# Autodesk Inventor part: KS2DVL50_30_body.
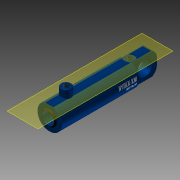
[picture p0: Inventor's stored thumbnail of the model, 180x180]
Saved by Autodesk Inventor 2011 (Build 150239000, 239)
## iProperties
Created: 2010-11
Document SubType Name: Modeling
Designer: TB
Mass: 405.061 g
Surface Area: 916.939 cm^2
Volume: 405.061 cm^3
Density: 1 g/cm^3
Author: TB
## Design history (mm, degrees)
sketch "Sketch2"
  geometry: L1 (-35, -3)-(-35, 3); L2 (-35, -9)-(-35, 9); L3 (-35, 0)-(-35, 30); L4 (-35, 30)-(-224, 30); L5 (-224, 30)-(-224, 30); L6 (-224, 30)-(-229, 30); L7 (-229, 30)-(-229, 19); L8 (-229, 19)-(-232, 16); L9 (-232, 16)-(-232, 15); L10 (-232, 15)-(-186, 15); L11 (-186, 15)-(-186, 25); L12 (-186, 25)-(-49, 25); L13 (-49, 25)-(-49, 0); L14 (-49, 0)-(-35, 0); L15 (-49, 0)-(-148.421, 0); L16 (-35, 9)-(-32, 12) reference; L17 (-32, 12)-(-35, 12) reference; L18 (-35, 12)-(-35, 9) reference; L19 (-32, 12)-(-35, 9) reference; L20 (-32, 12)-(-35, 12) reference; L21 (-35, 9)-(-35, 12) reference; L22 (-35, 9)-(-32, 12) reference; 1 further point
  constraints: 44 end point, 8 perpendicular, 6 parallel, 5 collinear, 2 horizontal, 2 vertical, 1 coincident, 1 midpoint, 1 point on line, 10 other
  dimensions: "DiaY" = 60 diameter of L4 L15; "DiaI" = 50 diameter of L12 L15; "d4" = 1 distance of L8.end L9.end; "d5" = 45 deg angle of L10 L8; "d6" = 3 distance between parallel lines of L7 L9; "DiaStang" = 30 diameter of L10 L15; "RindDia" = 60 diameter of L6 L15; "RingLengde" = 5 distance of L5.end L6.end; "RingTykk" = 43 distance between parallel lines of L11 L7; "KroppLengde" = 194 distance between parallel lines of L7 L3 (derived); "BunnTykkelse" = 14 distance between parallel lines of L13 L3
revolve "Kropp" sketch "Sketch2" stored, may be unused: angle "d13" = 90 deg
sketch "Sketch3"
  geometry: L1 (-49, -25)-(-49, 25) reference; L2 (-49, 0.01)-(-149, 0.01); L3 (-149, -0.01)-(-49, -0.01); A1 r 0.01 centre (-149, 0) between (-149, 0.01) and (-149, -0.01); A2 r 0.01 centre (-49, 0) between (-49, -0.01) and (-49, 0.01); 2 further points
  constraints: 4 end point, 4 point on circle, 4 tangent, 2 centre point, 1 coincident, 1 midpoint, 1 parallel, 1 perpendicular
  dimensions: "d17" = 0.01 radius of A2; "d18" = 100 distance of L2.start L2.end (= Slaglengde)
feature "BaneTransitionalConstraint" sketch "Sketch3" dims "d19" = 2, "d20" = 0
sketch "Sketch6"
  geometry: L1 (-42, 0)-(42, 0) reference; L2 (9.367, 28.5)-(-9.367, 28.5); L3 (30, 0)-(30, 31.248); L4 (-30, 0)-(-30, -18.451); A1 r 30 centre (0, 0) between (9.367, 28.5) and (-9.367, 28.5) reference; 1 further point
  constraints: 6 end point, 4 point on circle, 2 tangent
  dimensions: "d30" = 28.5 distance from line of A1.centre L2 (computed from DiaY); "d31" = 0 deg angle of L1 L2 (computed from Vinkel_Plussport); "d37" = 90 deg angle of L2 L3; "d38" = 90 deg angle of L2 L4
  node "Projected Loop3"
workplane "Work Plane5"
sketch "Sketch7"
  geometry: L1 (9.367, -278.4)-(9.367, 46.4) reference; L2 (-19.633, -35)-(38.367, -35) reference; C1 r 12.5 at (9.367, -52.5); 1 further point
  constraints: 1 centre point, 1 point on line
  dimensions: "PortDia" = 25 diameter of C1
extrude "Extrusion2" cut sketch "Sketch7" stored distance "d34" = 1.5; taper "d35" = 0 deg
workplane "Work Plane7"
sketch "Sketch4" dims "d142" = 12.20713
  geometry: L1 (-16.68, -40)-(-16.68, -78.777); L2 (-16.68, -78.777)-(16.68, -78.777); L3 (16.68, -78.777)-(16.68, -40); L4 (16.68, -40)-(-16.68, -40); L5 (-40.643, -40)-(0, -40); L6 (-29, -35)-(29, -35) reference; L7 (0, -35)-(0, -40); 3 further points
  constraints: 4 end point, 2 midpoint, 1 perpendicular, 2 other
  dimensions: "d40" = 5 distance of L7.start L5.end
emboss "Emboss1" sketch "Sketch4" dims "d4" = 1, "d5" = 45 deg, "d6" = 3, "d22" = 0.2, "d23" = 0, "DiaI" = 50, "DiaY" = 60, "RindDia" = 60, "DiaStang" = 30, "RingTykk" = 43, "RingLengde" = 5, "KroppLengde" = 194 (derived), "BunnTykkelse" = 14
workplane "Work Plane8"
sketch "Sketch8"
  geometry: L1 (-29, -35)-(29, -35) reference; L2 (0, -35)-(0, -40); L3 (-5.906, -110.587)-(-5.906, -40); L4 (-5.906, -40)-(5.906, -40); L5 (5.906, -40)-(5.906, -110.587); L6 (5.906, -110.587)-(-5.906, -110.587); 3 further points
  constraints: 2 end point, 2 midpoint, 1 perpendicular, 2 other
  dimensions: "d42" = 5 distance of L2.start L2.end
emboss "Emboss2" sketch "Sketch8" dims "d4" = 1, "d5" = 45 deg, "d6" = 3, "d43" = 0.2, "d44" = 0, "DiaI" = 50, "DiaY" = 60, "RindDia" = 60, "DiaStang" = 30, "RingTykk" = 43, "RingLengde" = 5, "KroppLengde" = 194 (derived), "BunnTykkelse" = 14
sketch "Sketch9"
  geometry: A1 r 12.5 centre (9.367, -52.5) between (0, -60.776) and (18.735, -60.776) reference; 1 further point
hole "Hole1" sketch "Sketch9" at (9.367, -52.5) diameter "d45" = 14.95; stored, may be unused: countersink angle "d49" = 82 deg, drill point angle "d51" = 118 deg; dims "d46" = 6, "d47" = 3.023, "d48" = 2, "d50" = 15
workplane "Work Plane9"
sketch "Sketch10"
  geometry: L1 (-42, 0)-(42, 0) reference; L2 (0, 30)-(13.136, 30); L3 (0, 30)-(0, 31.79); L4 (12.5, 27.272)-(12.5, 48); L5 (12.5, 48)-(0, 48); L6 (0, 48)-(0, 30); L7 (0, 30)-(12.5, 27.272); C1 r 30 at (0, 0) reference; A1 r 30 centre (0, 0) between (0, 30) and (12.5, 27.272); 1 further point
  constraints: 12 end point, 4 perpendicular, 2 concentric, 2 point on circle, 1 centre point, 1 point on line, 1 tangent
  dimensions: "d53" = 0 deg angle of L1 L2 (computed from Vinkel_Minusport); "d54" = 25 diameter of L4 L3; "d55" = 18 distance between parallel lines of L2 L5
revolve "Revolution2" sketch "Sketch10" stored, may be unused: angle "d56" = 90 deg
hole "Hole2" diameter "d59" = 14.95; stored, may be unused: countersink angle "d63" = 82 deg, drill point angle "d65" = 118 deg; dims "d57" = 10, "d58" = 10, "d60" = 6, "d61" = 3.023, "d62" = 2, "d64" = 14
fillet "Fillet1" dims "d66" = 2
sketch "Sketch15"
  geometry: L1 (12, -27.495)-(12, 27.495); L2 (-12, -27.495)-(-12, 27.495); A1 r 30 centre (0, 0) between (12, -27.495) and (-12, -27.495) reference; A2 r 29.998 centre (0, 0) between (12, 27.493) and (-12, 27.493); A3 r 29.998 centre (0, 0) between (-12, -27.493) and (12, -27.493)
  constraints: 8 point on circle, 4 end point, 4 point on line, 2 centre point
  dimensions: "d95" = 12 distance from line of L1 A1.centre; "d96" = 12 distance from line of A1.centre L2
extrude "Extrusion6" join sketch "Sketch15" distance "d97" = 62; taper "d98" = 0 deg
sketch "Sketch16"
  geometry: L1 (-35, 29.998)-(27, 29.998) reference; L2 (-35, -29.998)-(27, -29.998) reference; L3 (-228, -30)-(-35, -30) reference; L4 (-228, 30)-(-35, 30) reference; L5 (-35, 29.998)-(27, 29.998) reference; L6 (27, 29.998)-(27, 27.493) reference; L7 (27, -27.493)-(27, 27.493) reference; L8 (-279.911, 0)-(83.467, 0) reference; L9 (5.002, 29.998)-(27, 29.998); L10 (27, 29.998)-(27, 8); A1 r 21.998 centre (5.002, 8) between (27, 8) and (5.002, 29.998); 2 further points
  constraints: 4 end point, 4 tangent, 2 point on circle, 2 point on line, 1 centre point, 1 collinear, 1 perpendicular
  dimensions: "d137" = 8 distance from line of L10.end L8
extrude "Extrusion7" cut sketch "Sketch16" stored distance "d101" = 24; taper "d102" = 0 deg
mirror "Mirror1"
sketch "Sketch20"
  geometry: L1 (-35, 29.998)-(27, 29.998) reference; L2 (27, -27.493)-(27, 27.493) reference; L3 (27, 29.998)-(27, 27.493) reference; L4 (-47.543, 0)-(40.26, 0) reference; L5 (21.344, 15.366)-(2.962, 25.979); L6 (2.962, 25.979)-(-4, 29.998); A1 r 12.207 centre (15.24, 4.794) between (27, 8.069) and (21.344, 15.366); A2 r 30 centre (-12.038, -0.002) between (2.962, 25.979) and (-12.038, 29.998); 2 further points
  constraints: 4 end point, 4 point on circle, 3 point on line, 3 tangent, 2 centre point, 1 collinear, 1 midpoint
  dimensions: "d139" = 8.06884 distance from line of A1.start L4; "d140" = 22.66455 distance from line of L2 point (4.335, 0); "d141" = 30 deg angle of L1 L6; "d142" = 12.20713 radius of A1; "d143" = 30 radius of A2
extrude "Extrusion10" cut sketch "Sketch20" stored distance "d144" = 10; taper "d145" = 0 deg
mirror "Mirror2"
sketch "Sketch17"
  geometry: L1 (54.986, 0)-(0, 0) reference; L2 (27.493, -248.8)-(27.493, 113.8) reference; C1 r 18.5 at (27.493, 32); 1 further point
  constraints: 1 centre point, 1 point on line
  dimensions: "d103" = 37 diameter of C1; "d125" = 32 distance from line of C1.centre L1
extrude "Extrusion8" cut sketch "Sketch17" distance "d104" = 24; taper "d105" = 0 deg
pattern_circular "Circular Pattern1 Only Subsea" dims "d108" = 180 deg (derived)
workplane "Work Plane11"
sketch "Sketch18"
  geometry: L1 (0, -58.8)-(0, 9.8) reference; L2 (25, -49)-(-25, -49) reference; C1 r 12.5 at (0, -30); 1 further point
  constraints: 1 centre point
  dimensions: "DiaForsenkPlussPort" = 25 diameter of C1; "PlassPlussport" = 19 distance from line of L2 C1.centre
extrude "Extrusion9" cut sketch "Sketch18" stored distance "d113" = 10; taper "d114" = 0 deg
sketch "Sketch19"
  geometry: 8 further points
  constraints: 1 other
hole "Hole3" sketch "Sketch19" at (0, -30) diameter "d115" = 14.95; stored, may be unused: countersink angle "d119" = 90 deg, drill point angle "d121" = 118 deg; dims "d116" = 6, "d117" = 4, "d118" = 2, "d120" = 14.5
pattern_circular "Circular Pattern2 Only Subsea" dims angle "d123" = 360 deg
body "Solid1"
chamfer "Chamfer" distance "Chamfer" = 1; stored, may be unused: second distance "d15" = 2, angle "d16" = 45 deg
node "Projected Loop2"
body "Srf1"
node "Projected Loop4"
node "Projected Loop5"
node "Projected Loop10"
other parameters: "Slaglengde" = 100, "Forlengelse_rør" = 0, "Vinkel_Plussport" = 0 [user parameter; used in 1 equation term], "Vinkel_Minusport" = 0, "d32" = 90 deg, "d39" = 90 deg, "d41" = 90 deg, "PortMinusPlass" = -42, "Minusport2" = 180 deg, "ForsenkningPlussPort" = 28.2 (derived)
